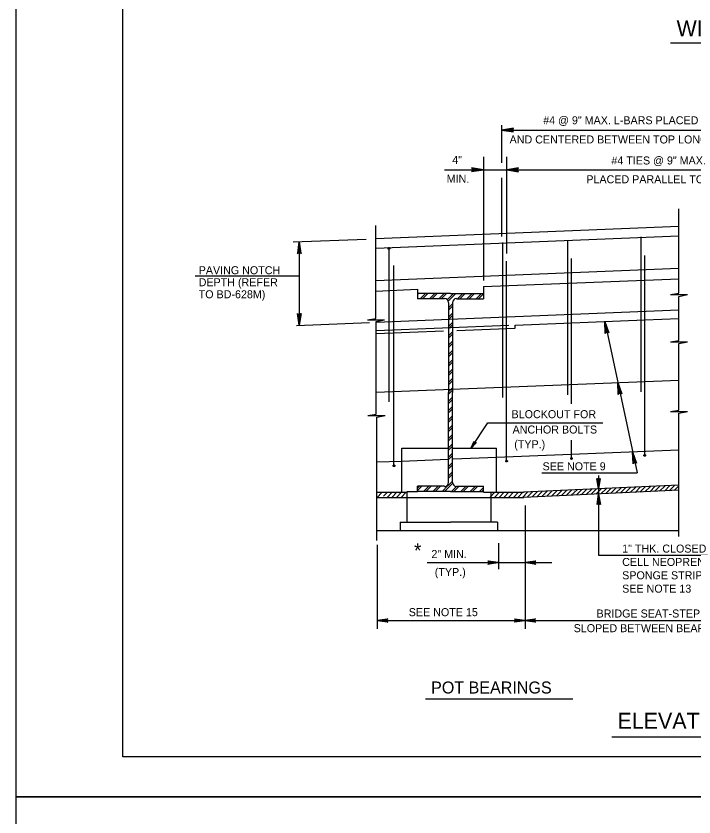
# Model space of a CAD drawing. Extents: x 640009 to 641706, y 298547 to 299735.
# Drawn here: x 640009.5 to 640263.3, y 299133.7 to 299433.7 of the extents above; entities that cross this region are included whole.
import ezdxf

# ---------------------------------------------------------------- set-up
doc = ezdxf.new("R2010")
doc.units = 0
doc.layers.add('1', color=7, linetype='Continuous')
doc.layers.add('PLT-BNDY', color=7, linetype='Continuous')

msp = doc.modelspace()

# ---------------------------------------------------------------- linework, layer by layer
at = {"layer": '1'}
for p, q in [((640049.47, 299156.17), (640049.47, 299720.17)), ((640049.47, 299156.17), (640049.47, 299720.17)), ((640254.55, 299423.68), (640459.83, 299423.68)), ((640191.28, 299392.84), (640191.28, 299378.72)), ((640191.28, 299390.99), (640337.03, 299390.99)), ((640184.53, 299380.98), (640184.53, 299334.68)), ((640193.15, 299380.98), (640193.15, 299344.68)), ((640169.89, 299376.11), (640351.8, 299376.11)), ((640191.28, 299373.11), (640191.28, 299351.05)), ((640257.65, 299329.83), (640257.65, 299361.46)), ((640144.15, 299320.43), (640144.15, 299355.18)), ((640144.15, 299350.3), (640257.65, 299354.93)), ((640144.15, 299346.68), (640257.65, 299351.3)), ((640243.4, 299350.93), (640243.4, 299292.93)), ((640113.26, 299349.05), (640140.61, 299350.16)), ((640115.57, 299317.79), (640115.57, 299349.14)), ((640191.65, 299348.8), (640191.65, 299290.8)), ((640216.03, 299349.68), (640216.03, 299291.8)), ((640149.03, 299347.05), (640149.03, 299289.18)), ((640193.15, 299266.8), (640193.15, 299341.8)), ((640217.53, 299288.43), (640217.53, 299342.8)), ((640244.9, 299268.93), (640244.9, 299343.93)), ((640144.15, 299334.68), (640257.65, 299339.18)), ((640150.9, 299265.05), (640150.9, 299340.18)), ((640076.57, 299336.36), (640115.57, 299336.36)), ((640184.53, 299332.36), (640257.65, 299335.3)), ((640184.53, 299332.36), (640184.53, 299327.8)), ((640144.15, 299330.68), (640159.78, 299331.39)), ((640159.78, 299331.39), (640159.78, 299327.8)), ((640172.15, 299329.8), (640159.78, 299329.8)), ((640172.15, 299329.8), (640159.78, 299329.8)), ((640159.78, 299329.8), (640159.78, 299327.8)), ((640172.15, 299329.8), (640159.78, 299329.8)), ((640159.78, 299329.8), (640159.78, 299328.8)), ((640172.15, 299329.8), (640159.78, 299329.8)), ((640159.78, 299329.8), (640159.78, 299327.8)), ((640172.15, 299329.8), (640184.53, 299329.8)), ((640172.15, 299329.8), (640184.53, 299329.8)), ((640172.15, 299329.8), (640184.53, 299329.8)), ((640172.15, 299329.8), (640184.53, 299329.8)), ((640184.53, 299329.8), (640184.53, 299327.8)), ((640184.53, 299329.8), (640184.53, 299328.8)), ((640184.53, 299329.8), (640184.53, 299327.8)), ((640254.53, 299329.33), (640257.65, 299329.83)), ((640254.53, 299329.33), (640260.9, 299329.33)), ((640257.65, 299328.68), (640260.9, 299329.33)), ((640257.78, 299329.33), (640257.78, 299329.33)), ((640169.9, 299327.8), (640159.78, 299327.8)), ((640169.9, 299327.8), (640159.78, 299327.8)), ((640169.9, 299327.8), (640159.78, 299327.8)), ((640171.4, 299326.3), (640171.4, 299292.68)), ((640171.4, 299326.3), (640171.4, 299292.68)), ((640171.4, 299326.3), (640171.4, 299292.68)), ((640172.9, 299326.3), (640172.9, 299292.68)), ((640172.9, 299326.3), (640172.9, 299292.68)), ((640172.9, 299326.3), (640172.9, 299292.68)), ((640174.4, 299327.8), (640184.53, 299327.8)), ((640174.4, 299327.8), (640184.53, 299327.8)), ((640174.4, 299327.8), (640184.53, 299327.8)), ((640257.65, 299320.36), (640257.65, 299328.68)), ((640144.28, 299318.96), (640257.65, 299323.58)), ((640141.03, 299319.93), (640144.15, 299320.43)), ((640244.9, 299319.85), (640257.65, 299320.36)), ((640257.65, 299312.19), (640257.65, 299320.36)), ((640114.53, 299317.75), (640141.89, 299318.86)), ((640141.03, 299319.93), (640147.4, 299319.93)), ((640144.28, 299319.3), (640147.4, 299319.93)), ((640144.28, 299319.93), (640144.28, 299319.93)), ((640144.28, 299284.55), (640144.28, 299319.3)), ((640144.28, 299315.93), (640194.03, 299317.93)), ((640196.4, 299317.93), (640244.9, 299319.85)), ((640196.4, 299316.8), (640196.4, 299317.93)), ((640229.9, 299319.3), (640242.01, 299262.54)), ((640144.28, 299314.8), (640169.53, 299315.8)), ((640174.53, 299315.93), (640196.4, 299316.8)), ((640254.53, 299311.69), (640257.65, 299312.19)), ((640254.53, 299311.69), (640260.9, 299311.69)), ((640257.65, 299311.04), (640260.9, 299311.69)), ((640257.78, 299311.69), (640257.78, 299311.69)), ((640257.65, 299286.06), (640257.65, 299311.04)), ((640144.28, 299292.8), (640257.65, 299297.32)), ((640171.4, 299259.05), (640171.4, 299292.68)), ((640171.4, 299259.05), (640171.4, 299292.68)), ((640171.4, 299259.05), (640171.4, 299292.68)), ((640172.9, 299259.05), (640172.9, 299292.68)), ((640172.9, 299259.05), (640172.9, 299292.68)), ((640172.9, 299259.05), (640172.9, 299292.68)), ((640141.15, 299284.05), (640144.28, 299284.55)), ((640254.53, 299285.56), (640257.65, 299286.06)), ((640254.53, 299285.56), (640260.9, 299285.56)), ((640257.65, 299284.91), (640260.9, 299285.56)), ((640257.65, 299238.7), (640257.65, 299284.91)), ((640257.78, 299285.56), (640257.78, 299285.56)), ((640141.15, 299284.05), (640147.65, 299284.05)), ((640144.4, 299284.05), (640144.4, 299284.05)), ((640144.53, 299283.43), (640147.65, 299284.05)), ((640144.53, 299237.18), (640144.53, 299283.43)), ((640179.78, 299271.68), (640186.15, 299281.3)), ((640186.15, 299281.3), (640229.15, 299281.3)), ((640217.53, 299267.8), (640217.53, 299274.8)), ((640153.9, 299255.18), (640153.9, 299271.8)), ((640153.9, 299271.8), (640171.4, 299271.8)), ((640172.9, 299271.8), (640189.4, 299271.8)), ((640189.4, 299255.3), (640189.4, 299271.8)), ((640189.4, 299268.46), (640257.65, 299271.18)), ((640144.53, 299266.68), (640153.9, 299267)), ((640153.9, 299267), (640171.15, 299267.71)), ((640173.13, 299267.79), (640189.4, 299268.46)), ((640206.36, 299262.54), (640242.01, 299262.54)), ((640227.64, 299261.58), (640227.64, 299231.8)), ((640169.9, 299257.55), (640159.78, 299257.55)), ((640159.78, 299255.55), (640159.78, 299257.55)), ((640169.9, 299257.55), (640159.78, 299257.55)), ((640159.78, 299255.55), (640159.78, 299257.55)), ((640169.9, 299257.55), (640159.78, 299257.55)), ((640159.78, 299255.55), (640159.78, 299257.55)), ((640174.4, 299257.55), (640184.53, 299257.55)), ((640174.4, 299257.55), (640184.53, 299257.55)), ((640174.4, 299257.55), (640184.53, 299257.55)), ((640184.53, 299255.55), (640184.53, 299257.55)), ((640184.53, 299255.55), (640184.53, 299257.55)), ((640184.53, 299255.55), (640184.53, 299257.55)), ((640257.65, 299257.91), (640199.53, 299255.3)), ((640144.53, 299255.3), (640155.78, 299255.3)), ((640155.78, 299255.55), (640159.78, 299255.55)), ((640155.78, 299255.3), (640155.78, 299244.05)), ((640172.15, 299255.55), (640159.78, 299255.55)), ((640172.15, 299255.55), (640159.78, 299255.55)), ((640172.15, 299255.55), (640159.78, 299255.55)), ((640172.15, 299255.55), (640184.53, 299255.55)), ((640172.15, 299255.55), (640184.53, 299255.55)), ((640172.15, 299255.55), (640184.53, 299255.55)), ((640184.53, 299255.3), (640187.28, 299255.3)), ((640187.28, 299255.3), (640187.28, 299244.05)), ((640187.28, 299255.3), (640199.53, 299255.3)), ((640257.65, 299256.03), (640199.65, 299253.3)), ((640199.86, 299255.3), (640199.65, 299255.3)), ((640144.53, 299253.3), (640199.65, 299253.3)), ((640200.15, 299250.3), (640200.15, 299204.09)), ((640153.28, 299244.05), (640153.28, 299240.93)), ((640153.28, 299244.05), (640172.15, 299244.05)), ((640189.78, 299244.05), (640172.15, 299244.05)), ((640189.78, 299244.05), (640189.78, 299240.93)), ((640144.53, 299240.93), (640257.65, 299240.93)), ((640144.65, 299235.55), (640144.65, 299204.09)), ((640190.15, 299236.18), (640190.15, 299226.55)), ((640227.64, 299231.8), (640302.25, 299231.8)), ((640163.44, 299228.93), (640190.15, 299228.93)), ((640190.15, 299228.93), (640200.15, 299228.93)), ((640200.15, 299228.93), (640210.15, 299228.93)), ((640144.65, 299207.26), (640200.03, 299207.26)), ((640200.03, 299207.26), (640321.65, 299207.26)), ((640162.78, 299177.9), (640218.01, 299177.9)), ((640232.63, 299163.7), (640287.78, 299163.7)), ((640835.47, 299156.17), (640049.47, 299156.17)), ((640835.47, 299156.17), (640049.47, 299156.17))]:
    msp.add_line(p, q, dxfattribs=at)
for points in [[(640195.57, 299391.51), (640195.39, 299391.19), (640191.32, 299390.97), (640195.57, 299391.51), (640195.78, 299391.7), (640191.32, 299390.97), (640195.39, 299390.77), (640195.55, 299390.47), (640191.32, 299390.97), (640195.78, 299390.25), (640195.55, 299390.47)], [(640180.28, 299375.58), (640180.46, 299375.89), (640184.53, 299376.11), (640180.28, 299375.58), (640180.07, 299375.39), (640184.53, 299376.11), (640180.46, 299376.31), (640180.3, 299376.62), (640184.53, 299376.11), (640180.07, 299376.84), (640180.3, 299376.62)], [(640197.44, 299376.63), (640197.27, 299376.32), (640193.2, 299376.1), (640197.44, 299376.63), (640197.65, 299376.82), (640193.2, 299376.1), (640197.27, 299375.9), (640197.43, 299375.59), (640193.2, 299376.1), (640197.65, 299375.37), (640197.43, 299375.59)], [(640116.09, 299344.85), (640115.78, 299345.03), (640115.55, 299349.09), (640116.09, 299344.85), (640116.28, 299344.64), (640115.55, 299349.09), (640115.35, 299345.03), (640115.05, 299344.87), (640115.55, 299349.09), (640114.83, 299344.64), (640115.05, 299344.87)], [(640149.03, 299346.55), (640149.03, 299346.55), (640149.03, 299346.68), (640149.15, 299346.68), (640149.15, 299346.68), (640149.15, 299346.55), (640149.15, 299346.55), (640149.15, 299346.43), (640149.03, 299346.43), (640149.03, 299346.43), (640148.9, 299346.55), (640148.9, 299346.68), (640148.9, 299346.68), (640149.03, 299346.68), (640149.03, 299346.8), (640149.15, 299346.8), (640149.28, 299346.68), (640149.28, 299346.55), (640149.28, 299346.43), (640149.15, 299346.3), (640149.15, 299346.3), (640149.03, 299346.3), (640148.9, 299346.43), (640148.78, 299346.55), (640148.78, 299346.68), (640148.9, 299346.68), (640148.9, 299346.8), (640149.03, 299346.8), (640149.15, 299346.8), (640149.28, 299346.8), (640149.4, 299346.68), (640149.4, 299346.68), (640149.4, 299346.55), (640149.4, 299346.43), (640149.28, 299346.43), (640149.28, 299346.3), (640149.15, 299346.3), (640149.03, 299346.3), (640149.03, 299346.3), (640148.9, 299346.3), (640148.78, 299346.3), (640148.78, 299346.43), (640148.78, 299346.55), (640148.78, 299346.55), (640148.78, 299346.68), (640148.78, 299346.8), (640148.9, 299346.8), (640149.03, 299346.8), (640149.15, 299346.93), (640149.15, 299346.8), (640149.28, 299346.8), (640149.03, 299346.55)], [(640159.78, 299329.43), (640160.15, 299329.8)], [(640160.78, 299327.8), (640162.78, 299329.8)], [(640161.65, 299327.8), (640163.65, 299329.8)], [(640164.28, 299327.8), (640166.28, 299329.8)], [(640165.15, 299327.8), (640167.15, 299329.8)], [(640167.78, 299327.8), (640169.78, 299329.8)], [(640168.65, 299327.8), (640170.65, 299329.8)], [(640170.9, 299327.43), (640173.28, 299329.8)], [(640171.28, 299326.93), (640174.15, 299329.8)], [(640174.78, 299327.8), (640176.78, 299329.8)], [(640175.65, 299327.8), (640177.65, 299329.8)], [(640178.28, 299327.8), (640180.28, 299329.8)], [(640179.15, 299327.8), (640181.15, 299329.8)], [(640181.78, 299327.8), (640183.78, 299329.8)], [(640182.65, 299327.8), (640184.53, 299329.68)], [(640184.4, 299327.8), (640184.53, 299327.93)], [(640171.4, 299324.43), (640172.9, 299325.93)], [(640171.4, 299323.55), (640172.9, 299325.05)], [(640116.09, 299322.08), (640115.78, 299321.9), (640115.55, 299317.83), (640116.09, 299322.08), (640116.28, 299322.29), (640115.55, 299317.83), (640115.35, 299321.9), (640115.05, 299322.06), (640115.55, 299317.83), (640114.83, 299322.29), (640115.05, 299322.06)], [(640171.4, 299320.93), (640172.9, 299322.43)], [(640171.4, 299320.05), (640172.9, 299321.55)], [(640171.4, 299317.43), (640172.9, 299318.93)], [(640171.4, 299316.55), (640172.9, 299318.05)], [(640230.28, 299314.99), (640230.47, 299315.18), (640229.9, 299319.3), (640230.28, 299314.99), (640230.09, 299314.8), (640229.9, 299319.3), (640230.84, 299315.37), (640231.22, 299315.18), (640229.9, 299319.3), (640231.4, 299314.99), (640231.22, 299315.18)], [(640171.4, 299313.93), (640172.9, 299315.43)], [(640171.4, 299313.05), (640172.9, 299314.55)], [(640171.4, 299310.43), (640172.9, 299311.93)], [(640171.4, 299309.55), (640172.9, 299311.05)], [(640171.4, 299306.93), (640172.9, 299308.43)], [(640171.4, 299306.05), (640172.9, 299307.55)], [(640171.4, 299303.43), (640172.9, 299304.93)], [(640171.4, 299302.55), (640172.9, 299304.05)], [(640171.4, 299299.93), (640172.9, 299301.43)], [(640171.4, 299299.05), (640172.9, 299300.55)], [(640171.4, 299296.43), (640172.9, 299297.93)], [(640171.4, 299295.55), (640172.9, 299297.05)], [(640235.16, 299292.11), (640235.35, 299292.3), (640234.79, 299296.42), (640235.16, 299292.11), (640234.97, 299291.92), (640234.79, 299296.42), (640235.72, 299292.48), (640236.1, 299292.3), (640234.79, 299296.42), (640236.29, 299292.11), (640236.1, 299292.3)], [(640171.4, 299292.93), (640172.9, 299294.43)], [(640171.4, 299292.05), (640172.9, 299293.55)], [(640171.4, 299289.43), (640172.9, 299290.93)], [(640171.4, 299288.55), (640172.9, 299290.05)], [(640171.4, 299285.93), (640172.9, 299287.43)], [(640171.4, 299285.05), (640172.9, 299286.55)], [(640171.4, 299282.43), (640172.9, 299283.93)], [(640171.4, 299281.55), (640172.9, 299283.05)], [(640171.4, 299278.93), (640172.9, 299280.43)], [(640171.4, 299278.05), (640172.9, 299279.55)], [(640171.4, 299275.43), (640172.9, 299276.93)], [(640171.4, 299274.55), (640172.9, 299276.05)], [(640171.4, 299271.93), (640172.9, 299273.43)], [(640171.4, 299271.05), (640172.9, 299272.55)], [(640181.65, 299273.8), (640181.4, 299273.8), (640179.78, 299271.68), (640181.65, 299273.8), (640181.9, 299273.93), (640179.78, 299271.68), (640181.15, 299274.05), (640181.15, 299274.18), (640179.78, 299271.68), (640181.03, 299274.43), (640181.15, 299274.18)], [(640171.4, 299268.43), (640172.9, 299269.93)], [(640240.69, 299266.18), (640240.88, 299266.37), (640240.32, 299270.49), (640240.69, 299266.18), (640240.5, 299265.99), (640240.32, 299270.49), (640241.25, 299266.56), (640241.63, 299266.37), (640240.32, 299270.49), (640241.82, 299266.18), (640241.63, 299266.37)], [(640244.9, 299269.05), (640244.9, 299269.18), (640244.9, 299269.18), (640244.9, 299269.18), (640245.03, 299269.18), (640245.03, 299269.05), (640245.03, 299269.05), (640244.9, 299268.93), (640244.9, 299268.93), (640244.78, 299268.93), (640244.78, 299269.05), (640244.78, 299269.18), (640244.78, 299269.18), (640244.78, 299269.3), (640244.9, 299269.3), (640245.03, 299269.3), (640245.03, 299269.18), (640245.15, 299269.05), (640245.15, 299268.93), (640245.03, 299268.93), (640244.9, 299268.8), (640244.78, 299268.8), (640244.65, 299268.93), (640244.65, 299269.05), (640244.65, 299269.18), (640244.65, 299269.3), (640244.78, 299269.3), (640244.9, 299269.3), (640245.03, 299269.3), (640245.15, 299269.3), (640245.15, 299269.3), (640245.15, 299269.18), (640245.15, 299269.05), (640245.15, 299268.93), (640245.15, 299268.93), (640245.03, 299268.8), (640245.03, 299268.8), (640244.9, 299268.8), (640244.78, 299268.8), (640244.65, 299268.8), (640244.65, 299268.93), (640244.53, 299268.93), (640244.53, 299269.05), (640244.53, 299269.18), (640244.53, 299269.18), (640244.65, 299269.3), (640244.65, 299269.3), (640244.78, 299269.43), (640244.9, 299269.43), (640245.03, 299269.43), (640245.03, 299269.3), (640244.9, 299269.05)], [(640171.4, 299267.55), (640172.9, 299269.05)], [(640171.4, 299264.93), (640172.9, 299266.43)], [(640193.15, 299266.93), (640193.15, 299267.05), (640193.15, 299267.05), (640193.28, 299267.05), (640193.28, 299267.05), (640193.28, 299266.93), (640193.28, 299266.93), (640193.28, 299266.8), (640193.15, 299266.8), (640193.03, 299266.8), (640193.03, 299266.93), (640193.03, 299267.05), (640193.03, 299267.05), (640193.15, 299267.05), (640193.15, 299267.18), (640193.28, 299267.18), (640193.4, 299267.05), (640193.4, 299266.93), (640193.4, 299266.8), (640193.28, 299266.68), (640193.15, 299266.68), (640193.03, 299266.68), (640193.03, 299266.8), (640192.9, 299266.93), (640192.9, 299267.05), (640193.03, 299267.18), (640193.03, 299267.18), (640193.15, 299267.18), (640193.28, 299267.18), (640193.4, 299267.18), (640193.4, 299267.05), (640193.53, 299267.05), (640193.53, 299266.93), (640193.53, 299266.8), (640193.4, 299266.8), (640193.4, 299266.68), (640193.28, 299266.68), (640193.15, 299266.68), (640193.03, 299266.68), (640193.03, 299266.68), (640192.9, 299266.8), (640192.9, 299266.8), (640192.9, 299266.93), (640192.9, 299267.05), (640192.9, 299267.05), (640192.9, 299267.18), (640193.03, 299267.18), (640193.15, 299267.3), (640193.15, 299267.3), (640193.28, 299267.18), (640193.4, 299267.18), (640193.15, 299266.93)], [(640217.53, 299267.93), (640217.53, 299267.93), (640217.53, 299268.05), (640217.53, 299268.05), (640217.65, 299268.05), (640217.65, 299267.93), (640217.65, 299267.8), (640217.65, 299267.8), (640217.53, 299267.8), (640217.4, 299267.8), (640217.4, 299267.93), (640217.4, 299267.93), (640217.4, 299268.05), (640217.53, 299268.05), (640217.53, 299268.05), (640217.65, 299268.05), (640217.78, 299268.05), (640217.78, 299267.93), (640217.78, 299267.8), (640217.65, 299267.68), (640217.53, 299267.68), (640217.4, 299267.68), (640217.28, 299267.8), (640217.28, 299267.93), (640217.28, 299268.05), (640217.28, 299268.05), (640217.4, 299268.18), (640217.53, 299268.18), (640217.65, 299268.18), (640217.78, 299268.18), (640217.78, 299268.05), (640217.78, 299268.05), (640217.78, 299267.93), (640217.78, 299267.8), (640217.78, 299267.68), (640217.78, 299267.68), (640217.65, 299267.68), (640217.53, 299267.55), (640217.4, 299267.68), (640217.4, 299267.68), (640217.28, 299267.68), (640217.28, 299267.8), (640217.15, 299267.93), (640217.15, 299267.93), (640217.28, 299268.05), (640217.28, 299268.18), (640217.28, 299268.18), (640217.4, 299268.18), (640217.53, 299268.18), (640217.65, 299268.18), (640217.78, 299268.18), (640217.53, 299267.93)], [(640150.9, 299265.18), (640150.9, 299265.3), (640150.9, 299265.3), (640151.03, 299265.3), (640151.03, 299265.3), (640151.15, 299265.3), (640151.03, 299265.18), (640151.03, 299265.05), (640150.9, 299265.05), (640150.9, 299265.05), (640150.78, 299265.18), (640150.78, 299265.3), (640150.9, 299265.3), (640150.9, 299265.43), (640151.03, 299265.43), (640151.03, 299265.43), (640151.15, 299265.3), (640151.15, 299265.18), (640151.15, 299265.05), (640151.15, 299265.05), (640151.03, 299264.93), (640150.9, 299265.05), (640150.78, 299265.05), (640150.65, 299265.18), (640150.65, 299265.3), (640150.78, 299265.43), (640150.9, 299265.43), (640150.9, 299265.55), (640151.03, 299265.55), (640151.15, 299265.43), (640151.28, 299265.43), (640151.28, 299265.3), (640151.28, 299265.18), (640151.28, 299265.05), (640151.28, 299265.05), (640151.15, 299264.93), (640151.03, 299264.93), (640151.03, 299264.93), (640150.9, 299264.93), (640150.78, 299264.93), (640150.65, 299265.05), (640150.65, 299265.05), (640150.65, 299265.18), (640150.65, 299265.3), (640150.65, 299265.3), (640150.65, 299265.43), (640150.78, 299265.43), (640150.9, 299265.55), (640151.03, 299265.55), (640151.03, 299265.55), (640151.15, 299265.43), (640150.9, 299265.18)], [(640171.4, 299264.05), (640172.9, 299265.55)], [(640171.4, 299261.43), (640172.9, 299262.93)], [(640171.4, 299260.55), (640172.9, 299262.05)], [(640228.1, 299260.32), (640227.85, 299260.19), (640227.64, 299256.57), (640228.1, 299260.32), (640228.22, 299260.45), (640227.64, 299256.57), (640227.48, 299260.19), (640227.23, 299260.31), (640227.64, 299256.57), (640226.97, 299260.43), (640227.23, 299260.31)], [(640159.78, 299255.93), (640161.4, 299257.55)], [(640159.78, 299256.8), (640160.53, 299257.55)], [(640162.03, 299255.55), (640164.03, 299257.55)], [(640162.9, 299255.55), (640164.9, 299257.55)], [(640165.53, 299255.55), (640167.53, 299257.55)], [(640166.4, 299255.55), (640168.4, 299257.55)], [(640169.03, 299255.55), (640171.15, 299257.8)], [(640169.9, 299255.55), (640173.03, 299258.68)], [(640171.28, 299257.8), (640172.9, 299259.43)], [(640172.53, 299255.55), (640174.53, 299257.55)], [(640173.4, 299255.55), (640175.4, 299257.55)], [(640176.03, 299255.55), (640178.03, 299257.55)], [(640176.9, 299255.55), (640178.9, 299257.55)], [(640179.53, 299255.55), (640181.53, 299257.55)], [(640180.4, 299255.55), (640182.4, 299257.55)], [(640241.28, 299255.18), (640243.28, 299257.3)], [(640243.03, 299255.3), (640245.15, 299257.43)], [(640244.9, 299255.43), (640247.03, 299257.43)], [(640246.78, 299255.43), (640248.78, 299257.55)], [(640248.53, 299255.55), (640250.65, 299257.68)], [(640250.4, 299255.68), (640252.53, 299257.68)], [(640252.28, 299255.68), (640254.28, 299257.8)], [(640254.03, 299255.8), (640256.15, 299257.93)], [(640255.9, 299255.93), (640257.51, 299257.54)], [(640144.78, 299253.43), (640146.28, 299255.05)], [(640147.03, 299253.8), (640148.53, 299255.3)], [(640148.4, 299253.3), (640150.28, 299255.3)], [(640150.15, 299253.3), (640152.03, 299255.3)], [(640151.9, 299253.3), (640153.78, 299255.3)], [(640153.65, 299253.3), (640155.53, 299255.3)], [(640183.03, 299255.55), (640184.53, 299257.05)], [(640183.9, 299255.55), (640184.53, 299256.18)], [(640186.9, 299253.3), (640188.78, 299255.3)], [(640188.65, 299253.3), (640190.53, 299255.3)], [(640190.4, 299253.3), (640192.28, 299255.3)], [(640192.15, 299253.3), (640194.03, 299255.3)], [(640193.9, 299253.3), (640195.78, 299255.3)], [(640195.71, 299253.3), (640197.59, 299255.3)], [(640197.4, 299253.3), (640199.27, 299255.29)], [(640199.15, 299253.3), (640201.15, 299255.43)], [(640200.9, 299253.43), (640203.03, 299255.55)], [(640202.78, 299253.55), (640204.78, 299255.55)], [(640204.53, 299253.55), (640206.65, 299255.68)], [(640206.4, 299253.68), (640208.53, 299255.8)], [(640208.28, 299253.8), (640210.28, 299255.8)], [(640210.03, 299253.8), (640212.15, 299255.93)], [(640211.9, 299253.93), (640214.03, 299256.05)], [(640213.78, 299254.05), (640215.78, 299256.05)], [(640215.53, 299254.05), (640217.65, 299256.18)], [(640217.4, 299254.18), (640219.53, 299256.18)], [(640219.28, 299254.3), (640221.28, 299256.3)], [(640221.03, 299254.3), (640223.15, 299256.43)], [(640222.9, 299254.43), (640225.03, 299256.43)], [(640224.78, 299254.55), (640226.78, 299256.55)], [(640226.53, 299254.55), (640228.65, 299256.68)], [(640227.22, 299250.86), (640227.47, 299250.99), (640227.64, 299254.62), (640227.22, 299250.86), (640227.1, 299250.73), (640227.64, 299254.62), (640227.84, 299251), (640228.09, 299250.88), (640227.64, 299254.62), (640228.35, 299250.76), (640228.09, 299250.88)], [(640228.4, 299254.68), (640230.53, 299256.68)], [(640230.28, 299254.8), (640232.28, 299256.8)], [(640232.03, 299254.8), (640234.15, 299256.93)], [(640233.9, 299254.93), (640236.03, 299256.93)], [(640235.78, 299255.05), (640237.78, 299257.05)], [(640237.53, 299255.05), (640239.65, 299257.18)], [(640239.4, 299255.18), (640241.53, 299257.18)], [(640186.4, 299229.43), (640186.53, 299229.18), (640190.15, 299228.93), (640186.4, 299229.43), (640186.15, 299229.55), (640190.15, 299228.93), (640186.53, 299228.8), (640186.4, 299228.55), (640190.15, 299228.93), (640186.15, 299228.3), (640186.4, 299228.55)], [(640203.9, 299228.55), (640203.78, 299228.8), (640200.15, 299228.93), (640203.9, 299228.55), (640204.15, 299228.3), (640200.15, 299228.93), (640203.78, 299229.18), (640203.9, 299229.43), (640200.15, 299228.93), (640204.15, 299229.55), (640203.9, 299229.43)], [(640148.4, 299206.76), (640148.28, 299207.01), (640144.65, 299207.26), (640148.4, 299206.76), (640148.65, 299206.64), (640144.65, 299207.26), (640148.28, 299207.39), (640148.4, 299207.76), (640144.65, 299207.26), (640148.65, 299207.89), (640148.4, 299207.76)], [(640196.28, 299207.76), (640196.4, 299207.51), (640200.03, 299207.26), (640196.28, 299207.76), (640196.15, 299207.89), (640200.03, 299207.26), (640196.4, 299207.14), (640196.28, 299206.76), (640200.03, 299207.26), (640196.15, 299206.64), (640196.28, 299206.76)], [(640203.78, 299206.76), (640203.65, 299207.01), (640200.03, 299207.26), (640203.78, 299206.76), (640204.03, 299206.64), (640200.03, 299207.26), (640203.65, 299207.39), (640203.78, 299207.76), (640200.03, 299207.26), (640204.03, 299207.89), (640203.78, 299207.76)]]:
    msp.add_lwpolyline(points, dxfattribs=at)
for centre, start, end in [((640169.95, 299326.33), 0, 90), ((640169.95, 299326.33), 0, 90), ((640169.95, 299326.33), 0, 90), ((640174.41, 299326.33), 90, 180), ((640174.41, 299326.33), 90, 180), ((640174.41, 299326.33), 90, 180), ((640169.95, 299259.01), 270, 0), ((640169.95, 299259.01), 270, 0), ((640169.95, 299259.01), 270, 0), ((640174.41, 299259.01), 180, 270), ((640174.41, 299259.01), 180, 270), ((640174.41, 299259.01), 180, 270)]:
    msp.add_arc(centre, 1.49, start, end, dxfattribs=at)
at = {"layer": 'PLT-BNDY'}
for points in [[(640009.47, 299735.17), (640850.47, 299735.17), (640850.47, 299141.17), (640009.47, 299141.17)], [(640009.47, 299141.17), (640850.47, 299141.17), (640850.47, 298547.17), (640009.47, 298547.17)]]:
    msp.add_lwpolyline(points, close=True, dxfattribs=at)

# ---------------------------------------------------------------- texts
at = {"layer": '1'}
msp.add_text('WITHOUT BACKWALL WITH PAVING NOTCH', height=6, rotation=360, dxfattribs=at).set_placement((640256.81, 299426.09))
for s, height, p in [('#4 @ 9" MAX. L-BARS PLACED PARALLEL TO', 3, (640206.87, 299393.13)), ('AND CENTERED BETWEEN TOP LONGITUDINAL SLAB BARS', 3, (640194.29, 299385.95)), ('4"', 3, (640172.81, 299378.28)), ('#4 TIES @ 9" MAX.', 3, (640232.41, 299378.07)), ('MIN.', 3, (640170.73, 299371.21)), ('PLACED PARALLEL TO BEAMS', 3, (640223.02, 299371.03)), ('PAVING NOTCH', 3, (640077.87, 299336.96)), ('DEPTH (REFER', 3, (640077.87, 299332.46)), ('TO BD-628M)', 3, (640077.87, 299327.96)), ('BLOCKOUT FOR', 3, (640195.03, 299283.05)), ('ANCHOR BOLTS', 3, (640195.4, 299277.3)), ('(TYP.)', 3, (640196.03, 299271.8)), ('SEE NOTE 9', 3, (640206.64, 299263.52)), ('*', 5.35, (640158.49, 299230.82)), ('2" MIN.', 3, (640165.02, 299230.66)), ('1" THK. CLOSED', 3, (640236.45, 299232.7)), ('CELL NEOPRENE', 3, (640236.45, 299227.7)), (' (TYP.)', 3, (640165.16, 299223.93)), ('SPONGE STRIP (CONT.),', 3, (640236.45, 299222.7)), ('SEE NOTE 13', 3, (640236.45, 299217.7)), ('SEE NOTE 15', 3, (640156.53, 299208.89)), ('BRIDGE SEAT-STEPPED OR', 3, (640226.85, 299208.39)), ('SLOPED BETWEEN BEARING AREAS', 3, (640218.28, 299202.89)), ('POT BEARINGS', 4.5, (640164.9, 299179.92)), ('ELEVATION', 6, (640234.69, 299166.7))]:
    msp.add_text(s, height=height, dxfattribs=at).set_placement(p)

doc.saveas('drawing.dxf')
